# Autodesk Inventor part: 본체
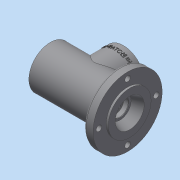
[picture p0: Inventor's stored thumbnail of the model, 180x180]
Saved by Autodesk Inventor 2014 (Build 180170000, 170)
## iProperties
Created: 2016-08
Part Number: 본체
Material: 일반
Document SubType Name: Modeling
Designer: 406-9
Density: 1 g/cm^3
Appearance: 기본값
Author: 406-9
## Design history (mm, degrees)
sketch "스케치1"
  geometry: L1 (-57.5, 0)-(57.5, 0); L2 (-57.5, 0)-(-57.5, 31); L3 (-57.5, 31)-(41.5, 31); L4 (41.5, 31)-(41.5, 50); L5 (41.5, 50)-(54.5, 50); L6 (54.5, 50)-(54.5, 31); L7 (54.5, 31)-(57.5, 31); L8 (57.5, 31)-(57.5, 0); 2 further points
  constraints: 16 end point, 4 parallel, 2 perpendicular, 1 coincident, 1 collinear, 1 horizontal, 1 midpoint
  dimensions: "d0" = 115 distance of L1.start L1.end; "d1" = 62 diameter of L3 L1; "d2" = 62 diameter of L7 L1; "d3" = 3 distance of L6.end L7.end; "d4" = 13 distance of L4.end L5.end; "d5" = 100 diameter of L5 L1
revolve "회전1" sketch "스케치1" stored, may be unused: angle "d6" = 90 deg
sketch "스케치2"
  geometry: A1 r 41.5 centre (0, 0) between (0, 41.5) and (0, -41.5); 3 further points
  constraints: 4 point on circle, 2 horizontal alignment, 2 vertical alignment, 1 centre point, 1 coincident
  dimensions: "d7" = 83 diameter of A1
hole "구멍1" sketch "스케치2" at (0, 41.5), (0, -41.5), (-41.5, 0), (41.5, 0) diameter "d8" = 8; stored, may be unused: countersink angle "d12" = 90 deg, drill point angle "d14" = 118 deg; dims "d9" = 6, "d10" = 4, "d11" = 2, "d13" = 8
sketch "스케치4"
  geometry: 2 further points
  constraints: 1 coincident
hole "구멍2" sketch "스케치4" at (0, 0) diameter "d61" = 40.376; stored, may be unused: countersink angle "d65" = 90 deg, drill point angle "d67" = 0 deg; dims "d62" = 9, "d63" = 4, "d64" = 2, "d66" = 9
sketch "스케치5"
  geometry: C1 r 24 at (0, 0); 1 further point
  constraints: 1 centre point, 1 coincident
  dimensions: "d68" = 48 diameter of C1
extrude "돌출1" cut sketch "스케치5" distance "d69" = 3; taper "d70" = 0 deg
sketch "스케치6"
  geometry: C1 r 20 at (0, 0); 1 further point
  constraints: 1 centre point, 1 coincident
  dimensions: "d71" = 40 diameter of C1
extrude "돌출2" cut sketch "스케치6" distance "d72" = 9; taper "d73" = 0 deg
sketch "스케치9"
  geometry: C1 r 17.5 at (0, 0); 1 further point
  constraints: 1 centre point, 1 coincident
  dimensions: "d77" = 35 diameter of C1
extrude "돌출4" cut sketch "스케치9" distance "d78" = 3.25; taper "d79" = 0 deg
sketch "스케치10"
  geometry: C1 r 18.5 at (0, 0); 1 further point
  constraints: 1 centre point, 1 coincident
  dimensions: "d80" = 37 diameter of C1
extrude "돌출5" cut sketch "스케치10" distance "d81" = 1.75; taper "d82" = 0 deg
sketch "스케치11"
  geometry: L1 (-31.5, -18.5)-(-31.5, 18.5) reference; L2 (-31.5, 0)-(57.5, 0); L3 (-31.5, 0.096)-(-31.5, 17.5); L4 (57.5, 21)-(43.5, 16); L5 (43.5, 16)-(43.5, 12.904); L6 (42.8, 12.5)-(36.2, 12.5); L7 (33.5, 16.5)-(28.5, 16.5); L8 (28.5, 16.5)-(28.5, 17.5); L9 (57.5, -31)-(57.5, 31) reference; L10 (42.8, 12.5)-(43.5, 12.904); L11 (36.2, 12.5)-(36.2, 10); L12 (33.5, 16.5)-(33.5, 10); L13 (33.5, 10)-(36.2, 10); L14 (28.5, 16.5)-(28.5, 0); L15 (57.5, 21)-(57.5, 0); 1 further point
  constraints: 26 end point, 4 perpendicular, 4 point on line, 3 parallel, 1 collinear, 1 horizontal, 1 midpoint
  dimensions: "d83" = 14 horizontal distance of L4.start L4.end; "d85" = 5 distance of L7.start L7.end; "d86" = 0.7 horizontal distance of L5.end L6.start; "d87" = 30 deg angle of L6 L10; "d90" = 2.7 distance of L12.end L11.end; "d91" = 42 diameter of L4.start L2; "d92" = 32 diameter of L4.end L2; "d93" = 25 diameter of L6 L2; "d94" = 20 diameter of L13 L2; "d95" = 33 diameter of L7 L2; "d100" = 7.3 horizontal distance of L5.end L6.end
revolve "회전2" sketch "스케치11" stored, may be unused: angle "d99" = 90 deg
sketch "스케치12"
  geometry: L1 (-31.5, -18.5)-(-31.5, 18.5) reference; L2 (-31.5, 0)-(28.5, 0); L3 (-31.5, 17.5)-(-17.5, 17.5); L4 (-17.5, 17.5)-(-17.5, 26); L5 (-17.5, 26)-(14.5, 26); L6 (14.5, 26)-(14.5, 17.5); L7 (14.5, 17.5)-(28.5, 17.5); L8 (28.5, 16.5)-(28.5, -16.5) reference; L9 (28.5, 17.5)-(28.5, 0); L10 (-31.5, 17.5)-(-31.5, 0); 1 further point
  constraints: 16 end point, 4 perpendicular, 2 collinear, 2 point on line, 1 horizontal, 1 midpoint, 1 parallel
  dimensions: "d101" = 60 distance of L2.start L2.end; "d102" = 35 diameter of L3 L2; "d103" = 52 diameter of L5 L2; "d104" = 35 diameter of L7 L2
revolve "회전3" sketch "스케치12" stored, may be unused: angle "d105" = 90 deg
node "작업 평면1"
sketch "스케치13"
  geometry: L1 (57.5, 31)-(57.5, -31) reference; C1 r 30 at (1.5, 0); 1 further point
  constraints: 1 centre point, 1 horizontal alignment
  dimensions: "d107" = 60 diameter of C1; "d108" = 56 distance from line of L1 C1.centre
extrude "돌출6" join sketch "스케치13" stored distance "d109" = 1.75; taper "d110" = 0 deg
sketch "스케치14"
  geometry: L1 (56, -50)-(56, 50) reference; L2 (-56, -31)-(-56, 31) reference; C1 r 19 at (0, 0); 1 further point
  constraints: 1 centre point, 1 horizontal alignment
  dimensions: "d111" = 38 diameter of C1; "d113" = 56 distance from line of C1.centre L2
extrude "돌출7" cut sketch "스케치14" stored distance "d114" = 1.75; taper "d115" = 0 deg
sketch "스케치15"
  geometry: C1 r 30 at (0, 0) reference; A1 r 24 centre (0, 0) between (-24, 0) and (24, 0); 3 further points
  constraints: 4 point on circle, 2 horizontal alignment, 2 vertical alignment, 1 centre point, 1 coincident
  dimensions: "d116" = 48 diameter of A1
hole "구멍3" sketch "스케치15" at (-24, 0), (24, 0), (0, 24), (0, -24) diameter "d117" = 3.242; stored, may be unused: countersink angle "d121" = 90 deg, drill point angle "d123" = 0 deg; dims "d118" = 8, "d119" = 4, "d120" = 2, "d122" = 10
node "작업 평면2"
sketch "스케치16"
  geometry: L1 (-57.5, -31)-(-57.5, 31) reference; L2 (-31.5, 50)-(28.5, 50) reference; 2 further points
  constraints: 1 other
  dimensions: "d125" = 56 distance from line of L1 point (-1.5, 40); "d126" = 10 distance from line of point (-1.5, 40) L2
feature "엠보싱1" sketch "스케치16" dims "d64" = 2, "d127" = 0.5, "d128" = 0
chamfer "모따기1" distance "d129" = 1; stored, may be unused: second distance "d130" = 2, angle "d131" = 45 deg
fillet "모깎기1" dims "d132" = 0.3
fillet "모깎기2" dims "d133" = 3
fillet "모깎기3" dims "d134" = 0.3
node "솔리드1"
